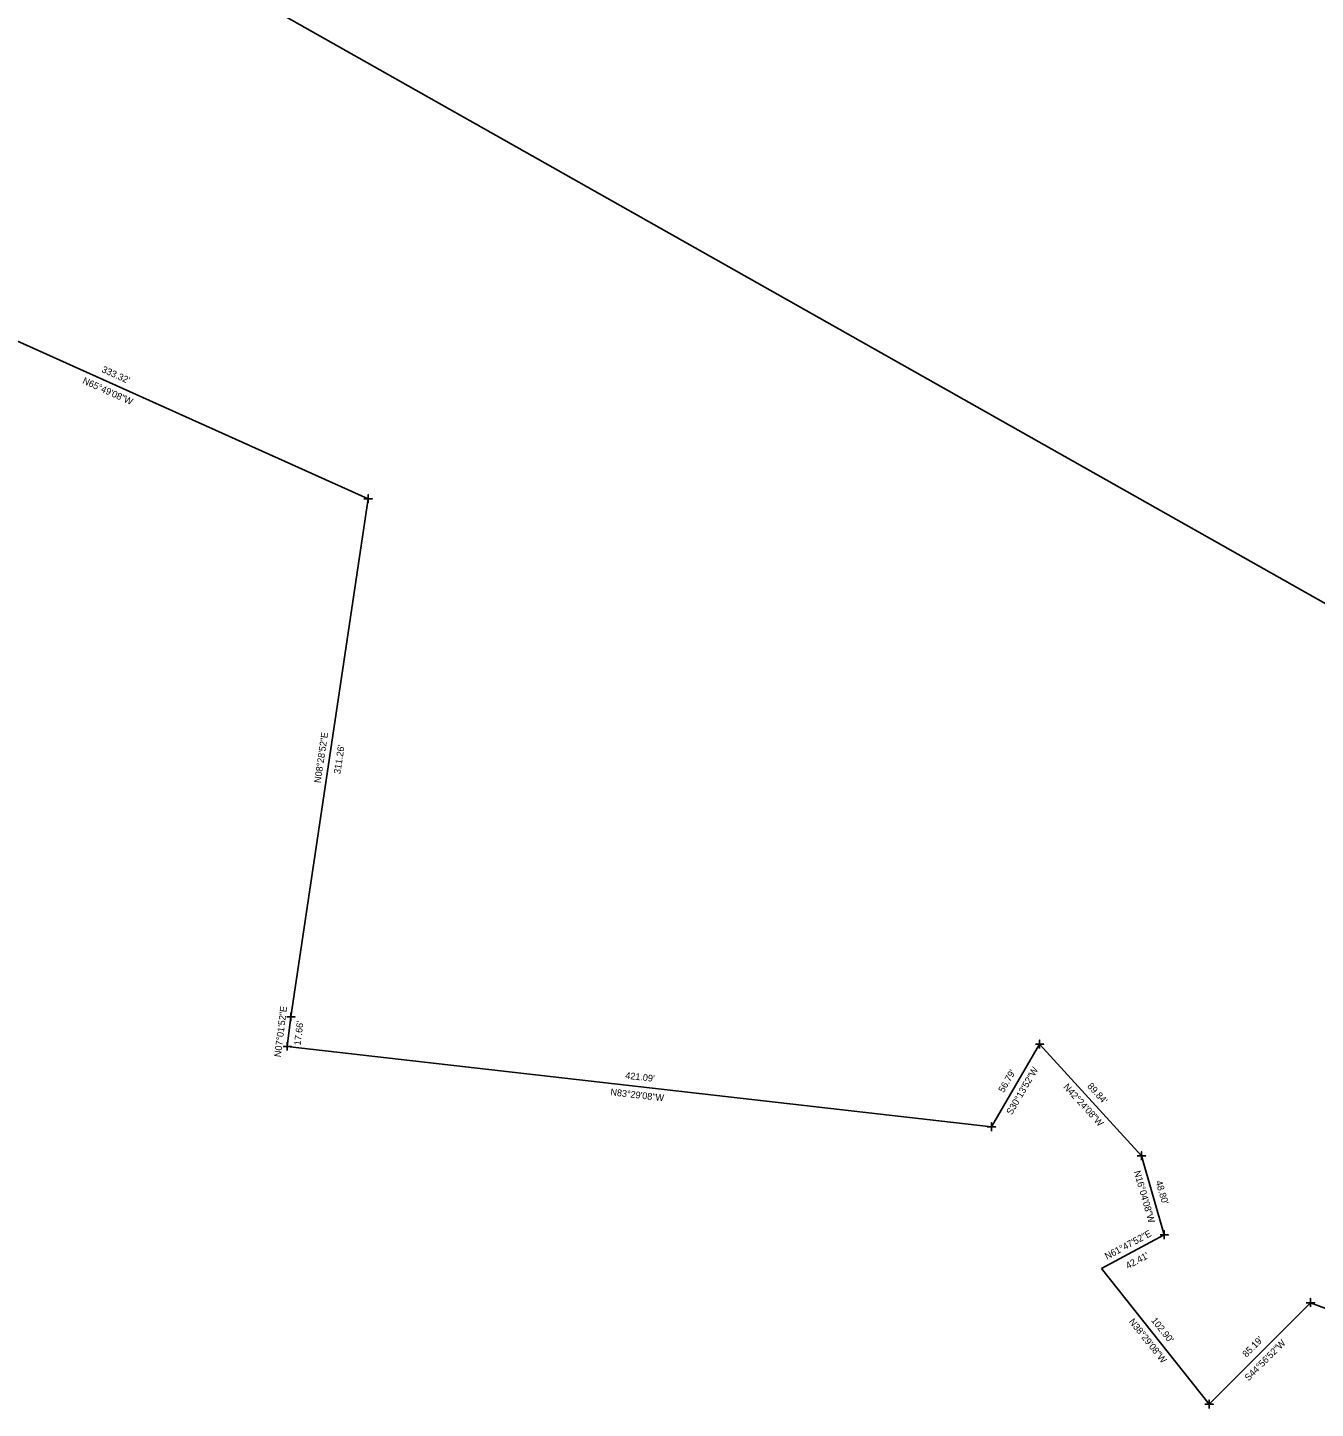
# Model space of a CAD drawing. Extents: x 1121294 to 1124558, y 901107 to 903080.
# Drawn here: x 1122062 to 1122827, y 901448 to 902268 of the extents above; entities that cross this region are included whole.
import ezdxf

# ---------------------------------------------------------------- set-up
doc = ezdxf.new("R2010")
doc.units = 0
for name, color, linetype in [('CTL Secondary Horizontal and Vertical CELL', 7, 'Continuous'), ('CTL Vertical Benchmark CELL', 7, 'Continuous'), ('Exist Survey Observation Group', 7, 'Continuous')]:
    doc.layers.add(name, color=color, linetype=linetype)

msp = doc.modelspace()

# ---------------------------------------------------------------- linework, layer by layer
at = {"layer": 'CTL Secondary Horizontal and Vertical CELL'}
for p, q in [((1121412.43, 902728.23), (1122865.6, 901907.59)), ((1122264.46, 901988.25), (1121960.39, 902124.78)), ((1122218.56, 901680.39), (1122264.46, 901988.25)), ((1122216.4, 901662.86), (1122218.56, 901680.39)), ((1122663.36, 901664.16), (1122634.77, 901615.09)), ((1122723.94, 901597.82), (1122663.36, 901664.16)), ((1122634.77, 901615.09), (1122216.4, 901662.86)), ((1122737.45, 901550.92), (1122723.94, 901597.82)), ((1122700.08, 901530.88), (1122737.45, 901550.92)), ((1122764.11, 901450.34), (1122700.08, 901530.88)), ((1122824.3, 901510.63), (1122764.11, 901450.34)), ((1122905.29, 901480.03), (1122824.3, 901510.63))]:
    msp.add_line(p, q, dxfattribs=at)
at = {"layer": 'CTL Vertical Benchmark CELL'}
for p, q in [((1122264.46, 901988.25), (1122264.46, 901988.25)), ((1122218.56, 901680.39), (1122218.56, 901680.39)), ((1122663.36, 901664.16), (1122663.36, 901664.16)), ((1122216.4, 901662.86), (1122216.4, 901662.86)), ((1122634.77, 901615.09), (1122634.77, 901615.09)), ((1122723.94, 901597.82), (1122723.94, 901597.82)), ((1122737.45, 901550.92), (1122737.45, 901550.92)), ((1122824.3, 901510.63), (1122824.3, 901510.63)), ((1122764.11, 901450.34), (1122764.11, 901450.34))]:
    msp.add_line(p, q, dxfattribs=at)
for points in [[(1122261.96, 901988.25), (1122266.96, 901988.25), (1122264.46, 901988.25), (1122264.46, 901990.75), (1122264.46, 901985.75)], [(1122216.06, 901680.39), (1122221.06, 901680.39), (1122218.56, 901680.39), (1122218.56, 901682.89), (1122218.56, 901677.89)], [(1122213.9, 901662.86), (1122218.9, 901662.86), (1122216.4, 901662.86), (1122216.4, 901665.36), (1122216.4, 901660.36)], [(1122660.86, 901664.16), (1122665.86, 901664.16), (1122663.36, 901664.16), (1122663.36, 901666.66), (1122663.36, 901661.66)], [(1122632.27, 901615.09), (1122637.27, 901615.09), (1122634.77, 901615.09), (1122634.77, 901617.59), (1122634.77, 901612.59)], [(1122721.44, 901597.82), (1122726.44, 901597.82), (1122723.94, 901597.82), (1122723.94, 901600.32), (1122723.94, 901595.32)], [(1122734.95, 901550.92), (1122739.95, 901550.92), (1122737.45, 901550.92), (1122737.45, 901553.42), (1122737.45, 901548.42)], [(1122821.8, 901510.63), (1122826.8, 901510.63), (1122824.3, 901510.63), (1122824.3, 901513.13), (1122824.3, 901508.13)], [(1122761.61, 901450.34), (1122766.61, 901450.34), (1122764.11, 901450.34), (1122764.11, 901452.84), (1122764.11, 901447.84)]]:
    msp.add_lwpolyline(points, dxfattribs=at)

# ---------------------------------------------------------------- texts
at = {"layer": 'Exist Survey Observation Group'}
for s, rotation, p in [("333.32'", 335.81897, (1122105.77, 902063.65)), ('N65°49\'08"W', 335.81897, (1122094.34, 902056.94)), ('N08°28\'52"E', 81.51897, (1122236.22, 901819.16)), ("311.26'", 81.51897, (1122247.93, 901824.48)), ('N07°01\'52"E', 82.96897, (1122212.57, 901656.34)), ("17.66'", 82.96897, (1122224.31, 901663.3)), ("421.09'", 353.48564, (1122417.08, 901643.75)), ("56.79'", 59.76897, (1122642.06, 901635.11)), ('S30°13\'52"W', 59.76897, (1122646.81, 901621.82)), ('N42°24\'08"W', 312.4023, (1122677.23, 901638.56)), ("89.84'", 312.4023, (1122691.43, 901639.02)), ('N83°29\'08"W', 353.48564, (1122408.22, 901633.89)), ('N16°04\'08"W', 286.06897, (1122719.34, 901588.45)), ("48.80'", 286.06897, (1122732.27, 901582.56)), ('N61°47\'52"E', 28.2023, (1122703.44, 901536.09)), ("42.41'", 28.2023, (1122715.9, 901530.52)), ('N38°29\'08"W', 308.48564, (1122716.22, 901499.29)), ("102.90'", 308.48564, (1122729.46, 901500)), ("85.19'", 45.0523, (1122786.28, 901477.89)), ('S44°56\'52"W', 45.0523, (1122787.51, 901463.83))]:
    msp.add_text(s, height=4.02, rotation=rotation, dxfattribs=at).set_placement(p)

doc.saveas('drawing.dxf')
